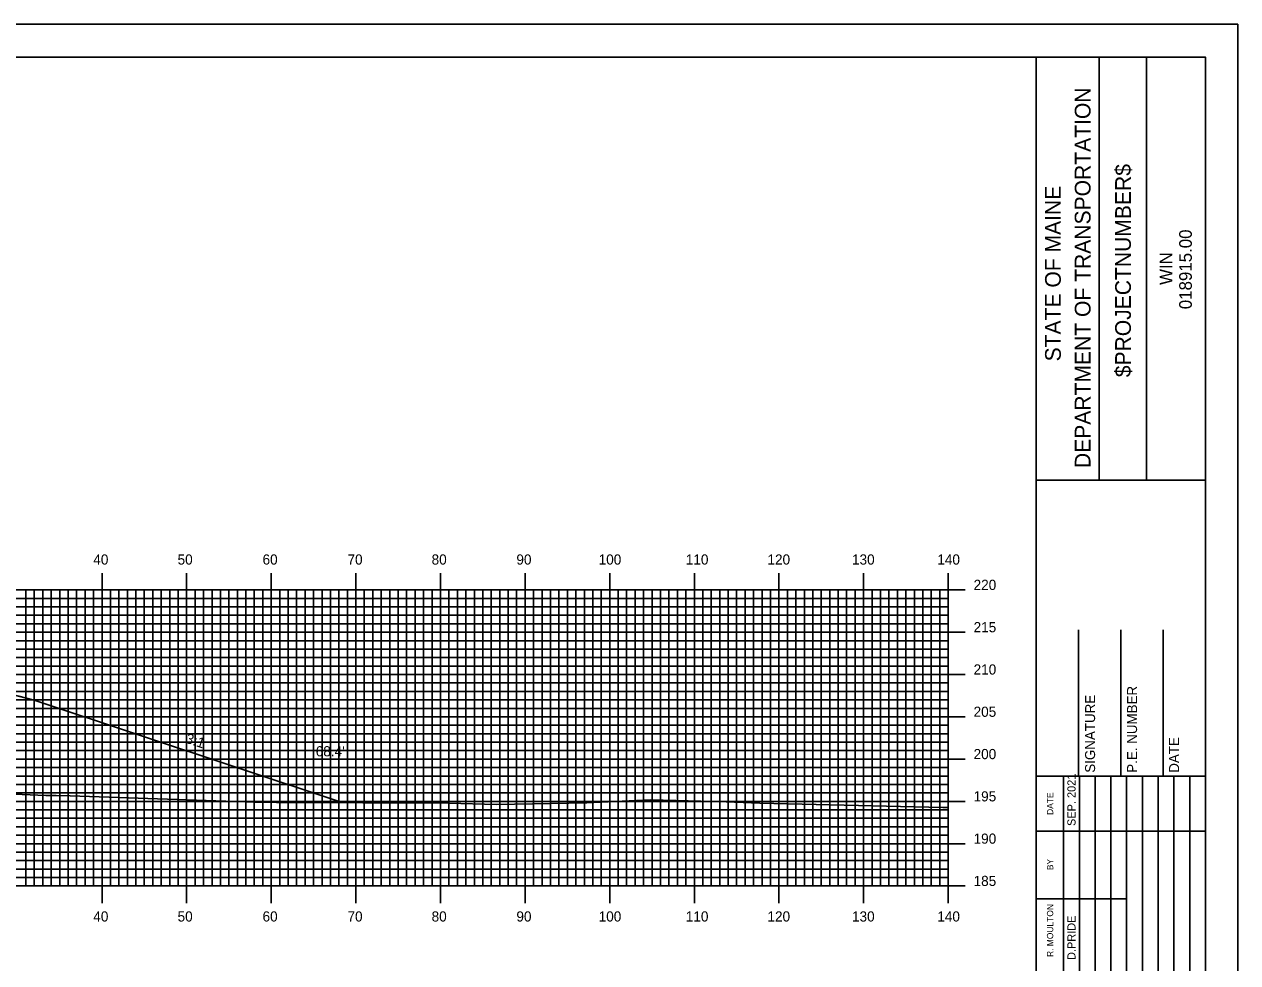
# Model space of a CAD drawing. Extents: x 1806258 to 1806601, y 442591 to 442811.
# Drawn here: x 1806454.5 to 1806597.9, y 442699.6 to 442810.5 of the extents above; entities that cross this region are included whole.
import ezdxf

# ---------------------------------------------------------------- set-up
doc = ezdxf.new("R2010")
doc.units = 0
for name, color, linetype in [('ANNOTATION', 7, 'Continuous'), ('BORDER', 7, 'Continuous'), ('D_Roadway_Centerline', 7, 'Continuous'), ('D_Roadway_SlopeLines', 7, 'Continuous'), ('D_Text_Standard', 7, 'Continuous'), ('H_V ANNOTATION', 7, 'Continuous'), ('MAJOR', 7, 'Continuous'), ('MINOR', 7, 'Continuous'), ('PLOT BOUNDARY', 7, 'Continuous'), ('S_Roadway_Centerline', 7, 'Continuous')]:
    doc.layers.add(name, color=color, linetype=linetype)

msp = doc.modelspace()

# ---------------------------------------------------------------- linework, layer by layer
at = {"layer": 'BORDER'}
for p, q in [((1806574.13, 442596.67), (1806574.13, 442806.67)), ((1806581.59, 442756.66), (1806581.59, 442806.66)), ((1806587.18, 442756.66), (1806587.18, 442806.66)), ((1806574.13, 442756.65), (1806594.13, 442756.65)), ((1806579.13, 442721.67), (1806579.13, 442738.97)), ((1806584.13, 442721.67), (1806584.13, 442738.97)), ((1806589.13, 442721.67), (1806589.13, 442738.97)), ((1806574.13, 442721.67), (1806594.13, 442721.67))]:
    msp.add_line(p, q, dxfattribs=at)
msp.add_lwpolyline([(1806274.13, 442596.67), (1806594.13, 442596.67), (1806594.13, 442806.67), (1806274.13, 442806.67)], close=True, dxfattribs=at)
for points in [[(1806577.36, 442715.17), (1806577.36, 442721.67)], [(1806579.23, 442686.68), (1806579.23, 442721.67)], [(1806581.09, 442721.67), (1806581.09, 442686.68)], [(1806582.95, 442686.68), (1806582.95, 442721.67)], [(1806584.82, 442686.68), (1806584.82, 442721.67)], [(1806586.68, 442686.68), (1806586.68, 442721.67)], [(1806588.54, 442686.68), (1806588.54, 442721.67)], [(1806590.41, 442686.68), (1806590.41, 442721.67)], [(1806592.27, 442686.68), (1806592.27, 442721.67)], [(1806577.36, 442686.68), (1806577.36, 442720.26)], [(1806574.13, 442715.17), (1806594.13, 442715.17)], [(1806574.13, 442707.17), (1806577.36, 442707.17)], [(1806577.36, 442707.17), (1806584.82, 442707.17)]]:
    msp.add_lwpolyline(points, dxfattribs=at)
at = {"layer": 'D_Roadway_Centerline'}
msp.add_lwpolyline([(1806367.07, 442722.43), (1806391.73, 442730.65), (1806393.56, 442731.1), (1806403.73, 442733.65), (1806411.73, 442733.97), (1806423.73, 442734.21), (1806435.73, 442733.97), (1806443.73, 442733.65), (1806453.91, 442731.1), (1806455.73, 442730.65), (1806492.1, 442718.53)], dxfattribs=at)
at = {"layer": 'D_Roadway_SlopeLines'}
msp.add_lwpolyline([(1806443.73, 442733.65), (1806455.73, 442730.65), (1806492.1, 442718.53)], dxfattribs=at)
at = {"layer": 'MAJOR'}
for p, q in [((1806463.73, 442745.67), (1806463.73, 442743.67)), ((1806473.73, 442745.67), (1806473.73, 442743.67)), ((1806483.73, 442745.67), (1806483.73, 442743.67)), ((1806493.73, 442745.67), (1806493.73, 442743.67)), ((1806503.73, 442745.67), (1806503.73, 442743.67)), ((1806513.73, 442745.67), (1806513.73, 442743.67)), ((1806523.73, 442745.67), (1806523.73, 442743.67)), ((1806533.73, 442745.67), (1806533.73, 442743.67)), ((1806543.73, 442745.67), (1806543.73, 442743.67)), ((1806553.73, 442745.67), (1806553.73, 442743.67)), ((1806563.73, 442745.67), (1806563.73, 442743.67)), ((1806283.73, 442743.67), (1806563.73, 442743.67)), ((1806283.73, 442743.67), (1806563.73, 442743.67)), ((1806463.73, 442708.67), (1806463.73, 442743.67)), ((1806473.73, 442708.67), (1806473.73, 442743.67)), ((1806483.73, 442708.67), (1806483.73, 442743.67)), ((1806493.73, 442708.67), (1806493.73, 442743.67)), ((1806503.73, 442708.67), (1806503.73, 442743.67)), ((1806513.73, 442708.67), (1806513.73, 442743.67)), ((1806523.73, 442708.67), (1806523.73, 442743.67)), ((1806533.73, 442708.67), (1806533.73, 442743.67)), ((1806543.73, 442708.67), (1806543.73, 442743.67)), ((1806553.73, 442708.67), (1806553.73, 442743.67)), ((1806565.74, 442743.67), (1806561.73, 442743.67)), ((1806563.73, 442708.67), (1806563.73, 442743.67)), ((1806563.73, 442708.67), (1806563.73, 442743.67)), ((1806283.73, 442738.67), (1806563.73, 442738.67)), ((1806565.74, 442738.67), (1806561.73, 442738.67)), ((1806283.73, 442733.67), (1806563.73, 442733.67)), ((1806565.74, 442733.67), (1806561.73, 442733.67)), ((1806283.73, 442728.67), (1806563.73, 442728.67)), ((1806565.74, 442728.67), (1806561.73, 442728.67)), ((1806283.73, 442723.67), (1806563.73, 442723.67)), ((1806565.74, 442723.67), (1806561.73, 442723.67)), ((1806283.73, 442718.67), (1806563.73, 442718.67)), ((1806565.74, 442718.67), (1806561.73, 442718.67)), ((1806283.73, 442713.67), (1806563.73, 442713.67)), ((1806565.74, 442713.67), (1806561.73, 442713.67)), ((1806283.73, 442708.67), (1806563.73, 442708.67)), ((1806283.73, 442708.67), (1806563.73, 442708.67)), ((1806463.73, 442706.66), (1806463.73, 442708.67)), ((1806473.73, 442706.66), (1806473.73, 442708.67)), ((1806483.73, 442706.66), (1806483.73, 442708.67)), ((1806493.73, 442706.66), (1806493.73, 442708.67)), ((1806503.73, 442706.66), (1806503.73, 442708.67)), ((1806513.73, 442706.66), (1806513.73, 442708.67)), ((1806523.73, 442706.66), (1806523.73, 442708.67)), ((1806533.73, 442706.66), (1806533.73, 442708.67)), ((1806543.73, 442706.66), (1806543.73, 442708.67)), ((1806553.73, 442706.66), (1806553.73, 442708.67)), ((1806565.74, 442708.67), (1806561.73, 442708.67)), ((1806563.73, 442706.66), (1806563.73, 442708.67))]:
    msp.add_line(p, q, dxfattribs=at)
at = {"layer": 'MINOR'}
for p, q in [((1806283.73, 442742.67), (1806563.73, 442742.67)), ((1806454.73, 442708.67), (1806454.73, 442743.67)), ((1806455.73, 442708.67), (1806455.73, 442743.67)), ((1806456.73, 442708.67), (1806456.73, 442743.67)), ((1806457.73, 442708.67), (1806457.73, 442743.67)), ((1806458.73, 442708.67), (1806458.73, 442743.67)), ((1806459.73, 442708.67), (1806459.73, 442743.67)), ((1806460.73, 442708.67), (1806460.73, 442743.67)), ((1806461.73, 442708.67), (1806461.73, 442743.67)), ((1806462.73, 442708.67), (1806462.73, 442743.67)), ((1806464.73, 442708.67), (1806464.73, 442743.67)), ((1806465.73, 442708.67), (1806465.73, 442743.67)), ((1806466.73, 442708.67), (1806466.73, 442743.67)), ((1806467.73, 442708.67), (1806467.73, 442743.67)), ((1806468.73, 442708.67), (1806468.73, 442743.67)), ((1806469.73, 442708.67), (1806469.73, 442743.67)), ((1806470.73, 442708.67), (1806470.73, 442743.67)), ((1806471.73, 442708.67), (1806471.73, 442743.67)), ((1806472.73, 442708.67), (1806472.73, 442743.67)), ((1806474.73, 442708.67), (1806474.73, 442743.67)), ((1806475.73, 442708.67), (1806475.73, 442743.67)), ((1806476.73, 442708.67), (1806476.73, 442743.67)), ((1806477.73, 442708.67), (1806477.73, 442743.67)), ((1806478.73, 442708.67), (1806478.73, 442743.67)), ((1806479.73, 442708.67), (1806479.73, 442743.67)), ((1806480.73, 442708.67), (1806480.73, 442743.67)), ((1806481.73, 442708.67), (1806481.73, 442743.67)), ((1806482.73, 442708.67), (1806482.73, 442743.67)), ((1806484.73, 442708.67), (1806484.73, 442743.67)), ((1806485.73, 442708.67), (1806485.73, 442743.67)), ((1806486.73, 442708.67), (1806486.73, 442743.67)), ((1806487.73, 442708.67), (1806487.73, 442743.67)), ((1806488.73, 442708.67), (1806488.73, 442743.67)), ((1806489.73, 442708.67), (1806489.73, 442743.67)), ((1806490.73, 442708.67), (1806490.73, 442743.67)), ((1806491.73, 442708.67), (1806491.73, 442743.67)), ((1806492.73, 442708.67), (1806492.73, 442743.67)), ((1806494.73, 442708.67), (1806494.73, 442743.67)), ((1806495.73, 442708.67), (1806495.73, 442743.67)), ((1806496.73, 442708.67), (1806496.73, 442743.67)), ((1806497.73, 442708.67), (1806497.73, 442743.67)), ((1806498.73, 442708.67), (1806498.73, 442743.67)), ((1806499.73, 442708.67), (1806499.73, 442743.67)), ((1806500.73, 442708.67), (1806500.73, 442743.67)), ((1806501.73, 442708.67), (1806501.73, 442743.67)), ((1806502.73, 442708.67), (1806502.73, 442743.67)), ((1806504.73, 442708.67), (1806504.73, 442743.67)), ((1806505.73, 442708.67), (1806505.73, 442743.67)), ((1806506.73, 442708.67), (1806506.73, 442743.67)), ((1806507.73, 442708.67), (1806507.73, 442743.67)), ((1806508.73, 442708.67), (1806508.73, 442743.67)), ((1806509.73, 442708.67), (1806509.73, 442743.67)), ((1806510.73, 442708.67), (1806510.73, 442743.67)), ((1806511.73, 442708.67), (1806511.73, 442743.67)), ((1806512.73, 442708.67), (1806512.73, 442743.67)), ((1806514.73, 442708.67), (1806514.73, 442743.67)), ((1806515.73, 442708.67), (1806515.73, 442743.67)), ((1806516.73, 442708.67), (1806516.73, 442743.67)), ((1806517.73, 442708.67), (1806517.73, 442743.67)), ((1806518.73, 442708.67), (1806518.73, 442743.67)), ((1806519.73, 442708.67), (1806519.73, 442743.67)), ((1806520.73, 442708.67), (1806520.73, 442743.67)), ((1806521.73, 442708.67), (1806521.73, 442743.67)), ((1806522.73, 442708.67), (1806522.73, 442743.67)), ((1806524.73, 442708.67), (1806524.73, 442743.67)), ((1806525.73, 442708.67), (1806525.73, 442743.67)), ((1806526.73, 442708.67), (1806526.73, 442743.67)), ((1806527.73, 442708.67), (1806527.73, 442743.67)), ((1806528.73, 442708.67), (1806528.73, 442743.67)), ((1806529.73, 442708.67), (1806529.73, 442743.67)), ((1806530.73, 442708.67), (1806530.73, 442743.67)), ((1806531.73, 442708.67), (1806531.73, 442743.67)), ((1806532.73, 442708.67), (1806532.73, 442743.67)), ((1806534.73, 442708.67), (1806534.73, 442743.67)), ((1806535.73, 442708.67), (1806535.73, 442743.67)), ((1806536.73, 442708.67), (1806536.73, 442743.67)), ((1806537.73, 442708.67), (1806537.73, 442743.67)), ((1806538.73, 442708.67), (1806538.73, 442743.67)), ((1806539.73, 442708.67), (1806539.73, 442743.67)), ((1806540.73, 442708.67), (1806540.73, 442743.67)), ((1806541.73, 442708.67), (1806541.73, 442743.67)), ((1806542.73, 442708.67), (1806542.73, 442743.67)), ((1806544.73, 442708.67), (1806544.73, 442743.67)), ((1806545.73, 442708.67), (1806545.73, 442743.67)), ((1806546.73, 442708.67), (1806546.73, 442743.67)), ((1806547.73, 442708.67), (1806547.73, 442743.67)), ((1806548.73, 442708.67), (1806548.73, 442743.67)), ((1806549.73, 442708.67), (1806549.73, 442743.67)), ((1806550.73, 442708.67), (1806550.73, 442743.67)), ((1806551.73, 442708.67), (1806551.73, 442743.67)), ((1806552.73, 442708.67), (1806552.73, 442743.67)), ((1806554.73, 442708.67), (1806554.73, 442743.67)), ((1806555.73, 442708.67), (1806555.73, 442743.67)), ((1806556.73, 442708.67), (1806556.73, 442743.67)), ((1806557.73, 442708.67), (1806557.73, 442743.67)), ((1806558.73, 442708.67), (1806558.73, 442743.67)), ((1806559.73, 442708.67), (1806559.73, 442743.67)), ((1806560.73, 442708.67), (1806560.73, 442743.67)), ((1806561.73, 442708.67), (1806561.73, 442743.67)), ((1806563.73, 442742.67), (1806561.73, 442742.67)), ((1806562.73, 442708.67), (1806562.73, 442743.67)), ((1806283.73, 442741.67), (1806563.73, 442741.67)), ((1806563.73, 442741.67), (1806561.73, 442741.67)), ((1806283.73, 442740.67), (1806563.73, 442740.67)), ((1806563.73, 442740.67), (1806561.73, 442740.67)), ((1806283.73, 442739.67), (1806563.73, 442739.67)), ((1806563.73, 442739.67), (1806561.73, 442739.67)), ((1806283.73, 442737.67), (1806563.73, 442737.67)), ((1806563.73, 442737.67), (1806561.73, 442737.67)), ((1806283.73, 442736.67), (1806563.73, 442736.67)), ((1806283.73, 442735.67), (1806563.73, 442735.67)), ((1806563.73, 442736.67), (1806561.73, 442736.67)), ((1806563.73, 442735.67), (1806561.73, 442735.67)), ((1806283.73, 442734.67), (1806563.73, 442734.67)), ((1806563.73, 442734.67), (1806561.73, 442734.67)), ((1806283.73, 442732.67), (1806563.73, 442732.67)), ((1806563.73, 442732.67), (1806561.73, 442732.67)), ((1806283.73, 442731.67), (1806563.73, 442731.67)), ((1806563.73, 442731.67), (1806561.73, 442731.67)), ((1806283.73, 442730.67), (1806563.73, 442730.67)), ((1806563.73, 442730.67), (1806561.73, 442730.67)), ((1806283.73, 442729.67), (1806563.73, 442729.67)), ((1806563.73, 442729.67), (1806561.73, 442729.67)), ((1806283.73, 442727.67), (1806563.73, 442727.67)), ((1806563.73, 442727.67), (1806561.73, 442727.67)), ((1806283.73, 442726.67), (1806563.73, 442726.67)), ((1806283.73, 442725.67), (1806563.73, 442725.67)), ((1806563.73, 442726.67), (1806561.73, 442726.67)), ((1806563.73, 442725.67), (1806561.73, 442725.67)), ((1806283.73, 442724.67), (1806563.73, 442724.67)), ((1806563.73, 442724.67), (1806561.73, 442724.67)), ((1806283.73, 442722.67), (1806563.73, 442722.67)), ((1806563.73, 442722.67), (1806561.73, 442722.67)), ((1806283.73, 442721.67), (1806563.73, 442721.67)), ((1806563.73, 442721.67), (1806561.73, 442721.67)), ((1806283.73, 442720.67), (1806563.73, 442720.67)), ((1806283.73, 442719.67), (1806563.73, 442719.67)), ((1806563.73, 442720.67), (1806561.73, 442720.67)), ((1806563.73, 442719.67), (1806561.73, 442719.67)), ((1806283.73, 442717.67), (1806563.73, 442717.67)), ((1806563.73, 442717.67), (1806561.73, 442717.67)), ((1806283.73, 442716.67), (1806563.73, 442716.67)), ((1806283.73, 442715.67), (1806563.73, 442715.67)), ((1806563.73, 442716.67), (1806561.73, 442716.67)), ((1806563.73, 442715.67), (1806561.73, 442715.67)), ((1806283.73, 442714.67), (1806563.73, 442714.67)), ((1806563.73, 442714.67), (1806561.73, 442714.67)), ((1806283.73, 442712.67), (1806563.73, 442712.67)), ((1806563.73, 442712.67), (1806561.73, 442712.67)), ((1806283.73, 442711.67), (1806563.73, 442711.67)), ((1806563.73, 442711.67), (1806561.73, 442711.67)), ((1806283.73, 442710.67), (1806563.73, 442710.67)), ((1806283.73, 442709.67), (1806563.73, 442709.67)), ((1806563.73, 442710.67), (1806561.73, 442710.67)), ((1806563.73, 442709.67), (1806561.73, 442709.67))]:
    msp.add_line(p, q, dxfattribs=at)
at = {"layer": 'PLOT BOUNDARY'}
msp.add_lwpolyline([(1806257.95, 442590.55), (1806597.95, 442590.55), (1806597.95, 442810.55), (1806257.95, 442810.55)], close=True, dxfattribs=at)
at = {"layer": 'S_Roadway_Centerline'}
msp.add_lwpolyline([(1806442.15, 442720.01), (1806457.09, 442719.38), (1806458.3, 442719.38), (1806459.98, 442719.33), (1806481.79, 442718.58), (1806484.34, 442718.55), (1806504.71, 442718.48), (1806510.34, 442718.3), (1806521.03, 442718.52), (1806528.56, 442718.85), (1806537.49, 442718.61), (1806541.47, 442718.48), (1806563.08, 442717.97), (1806563.49, 442717.96), (1806563.73, 442717.96)], dxfattribs=at)

# ---------------------------------------------------------------- texts
at = {"layer": 'ANNOTATION'}
msp.add_text('3:1', height=1.2, rotation=341.5652, dxfattribs=at).set_placement((1806473.52, 442725.63))
at = {"layer": 'BORDER'}
for s, height, p in [('DEPARTMENT OF TRANSPORTATION', 1.8635, (1806580.55, 442758.08)), ('$PROJECTNUMBER$', 1.8635, (1806585.32, 442768.82)), ('STATE OF MAINE', 1.8635, (1806577.04, 442770.69)), ('018915.00', 1.491, (1806592.52, 442776.86)), ('WIN', 1.491, (1806590.21, 442779.73)), ('SIGNATURE', 1.181, (1806581.09, 442722.06)), ('P.E. NUMBER', 1.1811, (1806586.05, 442722.06)), ('DATE', 1.181, (1806591.01, 442722.06)), ('SEP. 2021', 0.969, (1806578.78, 442715.76)), ('DATE', 0.743, (1806576.14, 442717.08)), ('BY', 0.743, (1806576.14, 442710.54)), ('R. MOULTON', 0.745, (1806576.14, 442700.28)), ('D.PRIDE', 0.969, (1806578.78, 442699.92))]:
    msp.add_text(s, height=height, rotation=90, dxfattribs=at).set_placement(p)
at = {"layer": 'D_Text_Standard'}
msp.add_text("68.4'", height=1.2, dxfattribs=at).set_placement((1806488.99, 442724))
at = {"layer": 'H_V ANNOTATION'}
for s, p in [('40', (1806462.7, 442746.67)), ('50', (1806472.66, 442746.67)), ('60', (1806482.7, 442746.67)), ('70', (1806492.74, 442746.67)), ('80', (1806502.68, 442746.67)), ('90', (1806512.7, 442746.67)), ('100', (1806522.42, 442746.67)), ('110', (1806532.72, 442746.67)), ('120', (1806542.37, 442746.67)), ('130', (1806552.36, 442746.67)), ('140', (1806562.44, 442746.67)), ('220', (1806566.73, 442743.67)), ('215', (1806566.73, 442738.67)), ('210', (1806566.73, 442733.67)), ('205', (1806566.73, 442728.67)), ('200', (1806566.73, 442723.67)), ('195', (1806566.73, 442718.67)), ('190', (1806566.73, 442713.67)), ('185', (1806566.73, 442708.67)), ('40', (1806462.7, 442704.47)), ('50', (1806472.66, 442704.47)), ('60', (1806482.7, 442704.47)), ('70', (1806492.74, 442704.47)), ('80', (1806502.68, 442704.47)), ('90', (1806512.7, 442704.47)), ('100', (1806522.42, 442704.47)), ('110', (1806532.72, 442704.47)), ('120', (1806542.37, 442704.47)), ('130', (1806552.36, 442704.47)), ('140', (1806562.44, 442704.47))]:
    msp.add_text(s, height=1.2, dxfattribs=at).set_placement(p)

doc.saveas('drawing.dxf')
